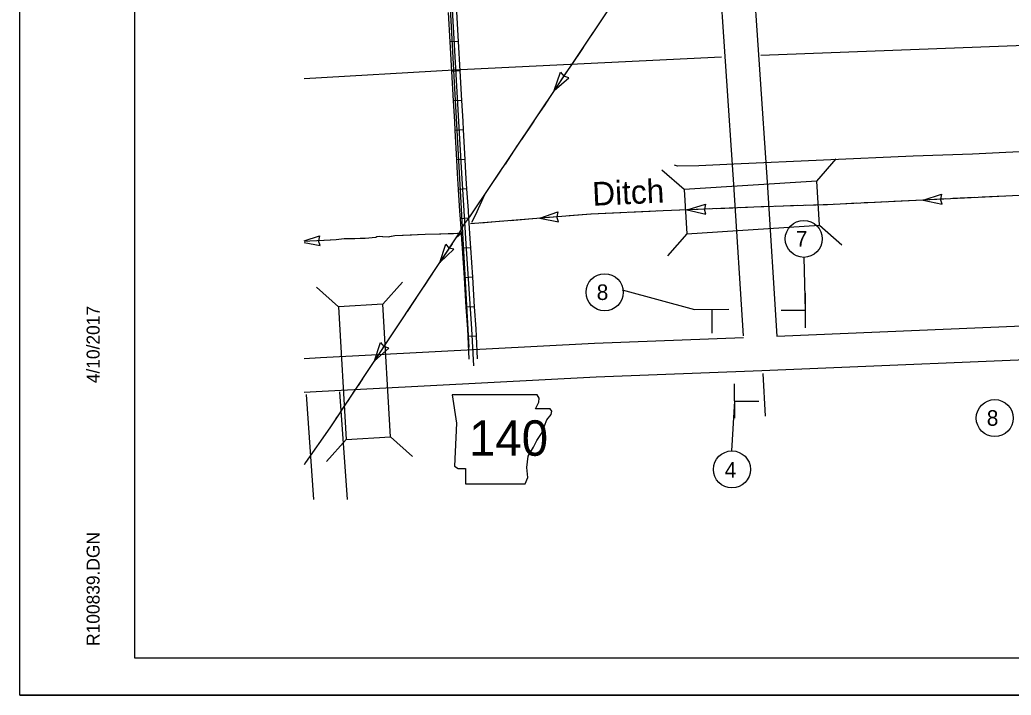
# Model space of a CAD drawing. Extents: x 9792 to 14027, y 9583 to 10649.
# Drawn here: x 9792 to 10326, y 9583 to 9947 of the extents above; entities that cross this region are included whole.
import ezdxf

# ---------------------------------------------------------------- set-up
doc = ezdxf.new("R2010")
doc.units = 0
for name, color, linetype in [('Default', 7, 'Continuous'), ('R_Border', 7, 'Continuous'), ('R_Border Notes', 7, 'Continuous'), ('R_MOT', 7, 'Continuous'), ('R_No Plot', 7, 'Continuous')]:
    doc.layers.add(name, color=color, linetype=linetype)

msp = doc.modelspace()

# ---------------------------------------------------------------- linework, layer by layer
at = {"layer": 'Default'}
for p, q in [((10028.63, 9934.97), (10024.12, 9934.71)), ((10029.55, 9919.08), (10025.03, 9918.82)), ((10080.21, 9908.59), (10083.54, 9918.38)), ((10080.21, 9908.59), (10087.99, 9915.4)), ((10083.54, 9918.38), (10085.35, 9916.31)), ((10087.99, 9915.4), (10085.38, 9916.29)), ((10030.47, 9903.19), (10025.95, 9902.93)), ((10031.37, 9887.29), (10026.85, 9887.05)), ((10032.22, 9871.4), (10027.71, 9871.16)), ((10221.64, 9859.74), (10232.15, 9871.69)), ((10150.17, 9855.14), (10138.22, 9865.65)), ((10033.16, 9855.54), (10028.65, 9855.25)), ((10279.02, 9849.47), (10288.87, 9852.64)), ((10288.87, 9852.64), (10288.29, 9849.95)), ((10151.82, 9844.16), (10161.69, 9847.25)), ((10161.69, 9847.25), (10161.09, 9844.56)), ((10279.02, 9849.47), (10289.14, 9847.29)), ((10289.14, 9847.29), (10288.29, 9849.91)), ((10034.19, 9839.65), (10029.68, 9839.36)), ((10072.38, 9839.64), (10082.13, 9843.11)), ((10082.13, 9843.11), (10081.63, 9840.41)), ((10082.56, 9837.78), (10081.63, 9840.37)), ((10151.82, 9844.16), (10161.91, 9841.9)), ((10161.91, 9841.9), (10161.09, 9844.53)), ((10072.38, 9839.64), (10082.56, 9837.78)), ((10223.17, 9835.91), (10235.12, 9825.4)), ((9945.36, 9827.43), (9953.72, 9830.26)), ((9953.72, 9830.26), (9953.18, 9827.56)), ((10151.7, 9831.32), (10141.19, 9819.37)), ((9945.36, 9826.66), (9954.07, 9824.92)), ((9954.07, 9824.92), (9953.18, 9827.53)), ((10018.5, 9815.88), (10021.79, 9825.69)), ((10021.79, 9825.69), (10023.43, 9823.48)), ((10035.22, 9823.78), (10030.7, 9823.48)), ((10018.5, 9815.88), (10026.04, 9822.96)), ((10026.04, 9822.96), (10023.43, 9823.48)), ((10036.26, 9807.89), (10031.75, 9807.6)), ((9963.96, 9791.98), (9952.08, 9802.56)), ((9987.8, 9793.36), (9998.38, 9805.25)), ((10037.31, 9792.01), (10032.79, 9791.72)), ((10038.29, 9776.1), (10033.78, 9775.87)), ((9983.26, 9762.87), (9986.56, 9772.67)), ((9986.56, 9772.67), (9988.38, 9770.6)), ((9991.02, 9769.71), (9988.41, 9770.58)), ((9983.26, 9762.87), (9991.02, 9769.71)), ((9968.11, 9720.48), (9957.53, 9708.6)), ((9991.94, 9721.87), (10003.83, 9711.28))]:
    msp.add_line(p, q, dxfattribs=at)
for points in [[(10372.72, 10344.1), (10366.54, 10335.43), (10325.02, 10273.75), (10310.92, 10253.12), (10254.25, 10168.62), (10227.89, 10128.94), (10198.35, 10085.67), (10174.1, 10049.28), (10157.07, 10023.95), (10144.94, 10004.9), (10117.75, 9964.69), (10034.56, 9840.36), (10031.76, 9836.82), (10029.03, 9831.74), (9959.2, 9726.67), (9946.2, 9707.99), (9945.36, 9706.7)], [(10034.32, 9769.93), (10026.01, 9919.57), (10017.42, 10079.87), (10005.93, 10239.15), (9999.81, 10326.08)], [(10036.84, 9760.09), (10035.83, 9780), (10032.81, 9825.93), (10031.67, 9843.62), (10030.36, 9863.91), (10028.86, 9891.88), (10022.97, 9993.71), (10022.44, 10000.07), (10021.12, 10020.55), (10018.14, 10079.19), (10013.08, 10157.21), (10011.35, 10187.24), (10010.56, 10197.07), (10007.69, 10238.48), (10006.31, 10258.56), (10003.01, 10325.68)], [(10168.56, 9980.14), (10176.81, 9857.92), (10182.05, 9776.37)], [(10186.65, 9980.73), (10194.86, 9859.1), (10200.19, 9776.13)], [(10024.12, 9934.71), (10023.2, 9950.59)], [(10028.63, 9934.97), (10027.71, 9950.85)], [(10104.55, 9944.96), (10097.91, 9935.04)], [(10191.59, 9927.55), (10357.48, 9933.87), (10458.9, 9938.45)], [(10025.03, 9918.82), (10024.12, 9934.71)], [(10029.55, 9919.08), (10028.63, 9934.97)], [(10095.69, 9931.73), (10089.06, 9921.81)], [(9945.36, 9915.01), (10026.01, 9919.63), (10170.38, 9926.63)], [(10025.95, 9902.93), (10025.03, 9918.82)], [(10030.47, 9903.19), (10029.55, 9919.08)], [(10086.84, 9918.51), (10080.21, 9908.59)], [(10077.99, 9905.28), (10074.68, 9900.32)], [(10026.85, 9887.05), (10026.6, 9891.76), (10025.95, 9902.93)], [(10031.37, 9887.29), (10031.11, 9892.01), (10030.47, 9903.19)], [(10074.68, 9900.32), (10071.36, 9895.36)], [(10069.14, 9892.05), (10062.51, 9882.13)], [(10832.49, 9891.39), (10784.49, 9890.48), (10714.48, 9887.33), (10684.45, 9885.72), (10678.34, 9886.13), (10672.89, 9890.2), (10561.16, 9884.14), (10518.75, 9882.64), (10510.89, 9882.1), (10438.7, 9878.39), (10434.41, 9878.52), (10426.28, 9879.37), (10355.17, 9876.54), (10345.29, 9876.18), (10305.62, 9874.14), (10273.65, 9873.17), (10176.99, 9868.85), (10158.16, 9868.01), (10146.56, 9867.82), (10144.94, 9868.2)], [(10027.71, 9871.16), (10026.85, 9887.05)], [(10032.22, 9871.4), (10031.37, 9887.29)], [(10060.29, 9878.82), (10053.66, 9868.9)], [(10028.65, 9855.25), (10028.1, 9863.78), (10027.71, 9871.16)], [(10033.16, 9855.54), (10032.62, 9864.04), (10032.22, 9871.4)], [(10634.73, 9865.98), (10602.82, 9864.76), (10572.26, 9863.38), (10554.99, 9862.34), (10523.54, 9860.87), (10444.25, 9857.09), (10430.48, 9856.51), (10403.55, 9855.57), (10323.51, 9851.66), (10230.51, 9847.09), (10187.67, 9845.66), (10138.94, 9843.62), (10099.83, 9841.86), (10035.15, 9836.64)], [(10051.44, 9865.6), (10044.81, 9855.68)], [(10029.68, 9839.36), (10029.41, 9843.47), (10028.65, 9855.25)], [(10034.19, 9839.65), (10033.92, 9843.76), (10033.16, 9855.54)], [(10042.59, 9852.37), (10037.66, 9841.24), (10035.69, 9837.44)], [(10306.84, 9850.84), (10294.92, 9850.25)], [(10322.74, 9851.62), (10310.82, 9851.03)], [(10176.39, 9845.19), (10167.72, 9844.83)], [(10184.24, 9845.52), (10180.64, 9845.37)], [(10195.55, 9845.93), (10191.78, 9845.8)], [(10211.45, 9846.46), (10199.53, 9846.06)], [(10227.36, 9846.99), (10215.43, 9846.59)], [(10243.26, 9847.72), (10231.34, 9847.13)], [(10253.19, 9848.21), (10247.23, 9847.91)], [(10259.15, 9848.5), (10253.19, 9848.21)], [(10275.05, 9849.28), (10263.13, 9848.69)], [(10290.95, 9850.06), (10279.02, 9849.47)], [(10035.22, 9823.78), (10035.06, 9826.08), (10034.19, 9839.65)], [(10084.28, 9840.6), (10072.38, 9839.64)], [(10100.15, 9841.87), (10099.83, 9841.86), (10088.25, 9840.92)], [(10116.04, 9842.59), (10104.12, 9842.05)], [(10131.94, 9843.3), (10120.02, 9842.77)], [(10147.84, 9843.99), (10138.94, 9843.62), (10135.92, 9843.48)], [(10157.78, 9844.41), (10151.82, 9844.16)], [(10163.74, 9844.66), (10157.78, 9844.41)], [(10030.7, 9823.48), (10030.55, 9825.79), (10029.68, 9839.36)], [(10036.69, 9836.76), (10035.15, 9836.64)], [(10052.55, 9838.04), (10040.66, 9837.08)], [(10062.47, 9838.84), (10056.52, 9838.36)], [(10068.42, 9839.32), (10062.47, 9838.84)], [(10029.03, 9831.74), (10028.54, 9831.52), (10025.86, 9831.34), (10010.7, 9830.93), (9994.26, 9830.22), (9990.69, 9829.53), (9987.82, 9829.63), (9985.83, 9829.92), (9984.54, 9829.63), (9984.05, 9829.23), (9978.39, 9828.73), (9972.74, 9828.63), (9967.08, 9828.63), (9962.62, 9828.04), (9956.17, 9827.74), (9948.54, 9827.24), (9945.36, 9827.07)], [(9987.4, 9829.69), (9985.83, 9829.92), (9984.54, 9829.63), (9984.05, 9829.23), (9978.39, 9828.73), (9975.68, 9828.68)], [(10003.24, 9830.61), (9994.26, 9830.22), (9991.36, 9829.66)], [(10019.14, 9831.16), (10010.7, 9830.93), (10007.21, 9830.78)], [(10030.18, 9831.63), (10025.86, 9831.34), (10023.12, 9831.27)], [(10030.18, 9831.63), (10027.31, 9829.14)], [(9955.83, 9827.72), (9948.54, 9827.24), (9945.36, 9827.07)], [(9971.7, 9828.63), (9967.08, 9828.63), (9962.62, 9828.04), (9959.81, 9827.91)], [(10025.1, 9825.82), (10021.8, 9820.85)], [(10036.26, 9807.89), (10035.22, 9823.78)], [(10021.8, 9820.85), (10018.5, 9815.88)], [(10031.75, 9807.6), (10030.7, 9823.48)], [(10016.29, 9812.57), (10009.69, 9802.63)], [(10032.79, 9791.72), (10031.75, 9807.6)], [(10037.31, 9792.01), (10036.26, 9807.89)], [(10007.49, 9799.32), (10000.88, 9789.37)], [(10033.78, 9775.87), (10033.57, 9779.87), (10032.79, 9791.72)], [(10038.29, 9776.1), (10038.09, 9780.13), (10037.31, 9792.01)], [(10200.15, 9776.13), (10366.57, 9783.08), (10382.19, 9783.73)], [(10034.39, 9763.75), (10033.78, 9775.87)], [(10038.91, 9763.99), (10038.29, 9776.1)], [(9954.25, 9764.54), (10101.89, 9772.26), (10182.09, 9775.4)], [(9989.87, 9772.81), (9983.26, 9762.87)], [(10192.11, 9757.69), (10373.2, 9765.25)], [(9945.36, 9764.12), (9954.3, 9764.54)], [(9955.2, 9746.48), (10102.72, 9754.19), (10192.09, 9757.69)], [(10192.54, 9756.07), (10193.91, 9732.94)], [(9976.79, 9753.13), (9974.45, 9749.61)], [(9945.36, 9746.02), (9955.15, 9746.48)], [(9946.43, 9744.77), (9950.5, 9688.06)], [(9964.46, 9746.19), (9968.63, 9688.06)], [(9972.25, 9746.3), (9968.94, 9741.33)], [(9968.94, 9741.33), (9965.64, 9736.36)], [(9963.44, 9733.04), (9962.52, 9731.67)]]:
    msp.add_lwpolyline(points, dxfattribs=at)
for points in [[(10151.7, 9831.32), (10223.17, 9835.91), (10221.64, 9859.74), (10150.17, 9855.14)], [(9991.94, 9721.87), (9987.8, 9793.36), (9963.96, 9791.98), (9968.11, 9720.48)], [(10025.16, 9744.52), (10027.46, 9729.23), (10026.45, 9706.02), (10028.49, 9704.75), (10032.32, 9704.75), (10032.32, 9696.59), (10064.45, 9696.61), (10065.98, 9699.92), (10065.46, 9705.28), (10066.23, 9711.4), (10069.03, 9716.24), (10070.81, 9719.81), (10073.36, 9723.64), (10074.89, 9727.72), (10076.16, 9731.03), (10078.45, 9733.84), (10078.96, 9735.63), (10077.94, 9736.9), (10070.04, 9736.9), (10071.82, 9740.47), (10072.08, 9742.76), (10071.02, 9744.52)]]:
    msp.add_lwpolyline(points, close=True, dxfattribs=at)
at = {"layer": 'R_Border'}
for p, q in [((9854.26, 9602.55), (9854.26, 10629.85)), ((9854.26, 9602.55), (9854.26, 9602.55)), ((11435.16, 9602.55), (9854.26, 9602.55))]:
    msp.add_line(p, q, dxfattribs=at)
at = {"layer": 'R_Border Notes'}
for p, q in [((10214.65, 9818.59), (10215.37, 9790)), ((10116.8, 9801.15), (10155.8, 9790.58)), ((10175.96, 9714.3), (10177.46, 9741.11))]:
    msp.add_line(p, q, dxfattribs=at)
for centre in [(10214.65, 9828.56), (10107.36, 9799.76), (10317.55, 9731.97), (10175.96, 9704.32)]:
    msp.add_circle(centre, 9.97, dxfattribs=at)
at = {"layer": 'R_MOT'}
for p, q in [((10215.33, 9799.22), (10215.41, 9780.69)), ((10155.8, 9790.58), (10174.33, 9790.66)), ((10165.02, 9790.62), (10165.08, 9777.7)), ((10215.37, 9790), (10202.45, 9789.94)), ((10177.5, 9731.88), (10177.41, 9750.41)), ((10177.46, 9741.11), (10190.37, 9741.16))]:
    msp.add_line(p, q, dxfattribs=at)
at = {"layer": 'R_No Plot'}
msp.add_line((9792.26, 9582.66), (11458.93, 9582.66), dxfattribs=at)
for points in [[(9792.23, 10649.32), (11458.93, 10649.32), (11458.93, 9582.63), (9792.23, 9582.63)], [(11023.86, 10629.85), (11023.86, 10580.45), (11202.52, 10580.45), (11202.52, 10565.85), (11318.52, 10565.85), (11318.52, 10444.19), (11435.16, 10444.19), (11435.16, 9602.55), (9854.26, 9602.55), (9854.26, 10629.85)]]:
    msp.add_lwpolyline(points, close=True, dxfattribs=at)

# ---------------------------------------------------------------- texts
at = {"layer": 'Default'}
msp.add_text('Ditch', height=12.732, rotation=2.6389, dxfattribs=at).set_placement((10100.96, 9846.38))
msp.add_text('140', height=19.098, dxfattribs=at).set_placement((10034.27, 9711.66))
at = {"layer": 'R_Border'}
for s, p in [('4/10/2017', (9835.22, 9750.76)), ('R100839.DGN', (9835.22, 9609.17))]:
    msp.add_text(s, height=7, rotation=90, dxfattribs=at).set_placement(p)
at = {"layer": 'R_Border Notes'}
for s, p in [('7', (10210.37, 9824.42)), ('8', (10103.08, 9795.62)), ('8', (10313.27, 9727.83)), ('4', (10172.04, 9699.84))]:
    msp.add_text(s, height=8.4, dxfattribs=at).set_placement(p)

doc.saveas('drawing.dxf')
